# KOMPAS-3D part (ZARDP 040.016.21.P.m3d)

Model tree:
1. Плоскость XY
2. Плоскость ZX
3. Плоскость ZY
4. Ось X
5. Ось Y
6. Ось Z
7. Начало координат
8. Булева операция:1
9. Булева операция:2
10. Булева операция:3
11. Булева операция:4
